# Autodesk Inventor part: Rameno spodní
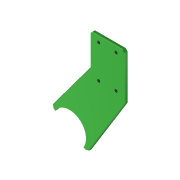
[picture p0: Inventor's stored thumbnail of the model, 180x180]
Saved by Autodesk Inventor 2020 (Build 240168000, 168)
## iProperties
Created: 2025-03
Part Number: Rameno spodní
Material: Ocel
Document SubType Name: Modeling
Designer: doma
Density: 7.85 g/cm^3
Appearance: Hladká – tmavá lesní zelená
Mass: 3367.65 g
Surface Area: 976.441 cm^2
Volume: 429 cm^3
Author: doma
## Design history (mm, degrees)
sketch "Náčrt1"
  geometry: L1 (3887.119, 474.261)-(3887.119, 547.261); L2 (3887.119, 474.261)-(3887.119, 444.062); L3 (4007.119, 394.261)-(4007.119, 547.261); L4 (4000.119, 554.261)-(3894.119, 554.261); L5 (4007.119, 547.261)-(4000.119, 554.261); L6 (3887.119, 547.261)-(3894.119, 554.261); L7 (4007.119, 394.261)-(3881.944, 191.421); L8 (3872.351, 189.206)-(3864.48, 194.064); L9 (3887.119, 444.062)-(3756.682, 268.243); L10 (3758.743, 259.315)-(3756.682, 268.243); L11 (3872.351, 189.206)-(3881.944, 191.421); L12 (3766.615, 254.458)-(3758.743, 259.315); A1 r 57.5 centre (3815.547, 224.261) between (3864.48, 194.064) and (3766.615, 254.458); 13 further points
  constraints: 24 end point, 2 point on circle, 1 centre point
extrude "Vysunutí1" new body sketch "Náčrt1" distance "d54" = 10; taper "d55" = 0 deg
sketch "Náčrt2" dims "d63" = 10, "d70" = 10
  geometry: L1 (-4007.119, 394.261)-(-4007.119, 547.261) reference; L2 (-4000.119, 554.261)-(-3894.119, 554.261) reference; 5 further points
  constraints: 1 horizontal, 1 vertical, 3 other
  dimensions: "d56" = 30 distance from line of L1 point (-3977.119, 534.261); "d57" = 20 distance from line of L2 point (-3977.119, 534.261); "d60" = 60 distance of point (-3977.119, 534.261) point (-3917.119, 534.261); "d67" = 115 distance of point (-3977.119, 534.261) point (-3977.119, 419.261)
hole "Díra1" sketch "Náčrt2" at (-3977.119, 534.261), (-3917.119, 534.261), (-3977.119, 419.261), (-3917.119, 419.261) diameter "d72" = 10.106; stored, may be unused: countersink angle "d76" = 90 deg, drill point angle "d78" = 118 deg; dims "d73" = 24, "d74" = 4, "d75" = 2, "d77" = 32.3
chamfer "Zkosení1" distance "d84" = 2; stored, may be unused: second distance "d85" = 2, angle "d86" = 45 deg
chamfer "Zkosení2" distance "d87" = 2; stored, may be unused: second distance "d88" = 2, angle "d89" = 45 deg; dims "d90" = 0, "d91" = 70, "d92" = 33.19871
node "Těleso1"
